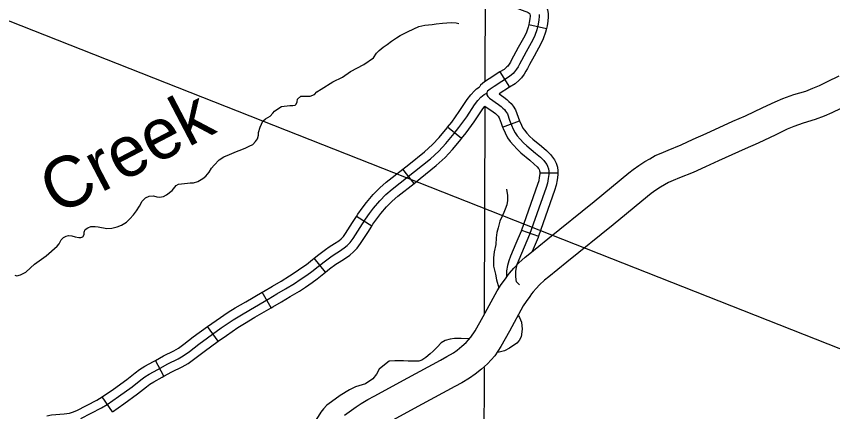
# Model space of a CAD drawing. Extents: x -3711 to 825, y -151 to 1050.
# Drawn here: x -2819.1 to -2743.1, y 325 to 361.8 of the extents above; entities that cross this region are included whole.
import ezdxf

# ---------------------------------------------------------------- set-up
doc = ezdxf.new("R2010")
doc.units = 0
for name, color, linetype in [('Level 10', 7, 'Continuous'), ('Level 32', 7, 'Continuous'), ('Level 35', 7, 'Continuous'), ('Level 5', 7, 'Continuous'), ('R_Dimension', 7, 'Continuous')]:
    doc.layers.add(name, color=color, linetype=linetype)

msp = doc.modelspace()

# ---------------------------------------------------------------- linework, layer by layer
at = {"layer": 'Level 10'}
for points in [[(-2788.528, 324.638), (-2787.441, 325.413), (-2786.955, 325.737), (-2786.36, 326.097), (-2785.754, 326.43), (-2782.623, 328.132), (-2779.582, 329.773), (-2778.996, 330.099), (-2778.387, 330.46), (-2778.024, 330.712), (-2777.586, 331.061), (-2777.207, 331.414), (-2776.745, 331.913), (-2776.368, 332.494), (-2775.603, 333.828), (-2774.296, 336.236), (-2773.934, 336.807), (-2773.544, 337.355), (-2773.352, 337.616), (-2773.155, 337.883), (-2772.765, 338.34), (-2772.29, 338.828), (-2771.7, 339.353), (-2771.274, 339.697), (-2769.576, 341.079), (-2765.277, 344.555), (-2762.057, 347.22), (-2761.633, 347.544), (-2761.114, 347.915), (-2760.566, 348.272), (-2760.102, 348.536), (-2759.587, 348.82), (-2759.033, 349.064), (-2758.395, 349.334), (-2757.177, 349.835), (-2756.06, 350.343), (-2754.853, 350.879), (-2752.358, 352.026), (-2751.177, 352.543), (-2749.574, 353.306), (-2748.427, 353.845), (-2747.704, 354.139), (-2746.688, 354.515), (-2745.583, 354.842), (-2744.912, 355.096), (-2744.302, 355.357), (-2743.556, 355.723), (-2742.47, 356.257)], [(-2742.321, 353.208), (-2743.134, 352.809), (-2743.864, 352.497), (-2744.688, 352.185), (-2745.803, 351.854), (-2746.69, 351.527), (-2747.303, 351.277), (-2748.376, 350.773), (-2750.012, 349.994), (-2751.21, 349.469), (-2753.699, 348.326), (-2754.911, 347.787), (-2756.064, 347.263), (-2757.317, 346.748), (-2757.922, 346.492), (-2758.342, 346.306), (-2758.733, 346.091), (-2759.107, 345.878), (-2759.533, 345.601), (-2759.966, 345.291), (-2760.312, 345.027), (-2763.503, 342.386), (-2767.811, 338.903), (-2769.51, 337.52), (-2769.888, 337.215), (-2770.352, 336.802), (-2770.692, 336.452), (-2770.96, 336.138), (-2771.097, 335.953), (-2771.273, 335.714), (-2771.608, 335.242), (-2771.879, 334.815), (-2773.155, 332.463), (-2773.976, 331.032), (-2774.527, 330.184), (-2775.22, 329.436), (-2775.753, 328.938), (-2776.352, 328.461), (-2776.872, 328.101), (-2777.6, 327.669), (-2778.236, 327.315), (-2781.289, 325.669), (-2784.41, 323.971)]]:
    msp.add_lwpolyline(points, dxfattribs=at)
at = {"layer": 'Level 32'}
for p, q in [((-2771.365, 361.028), (-2769.725, 360.659)), ((-2774.044, 356.615), (-2773.145, 355.194)), ((-2773.813, 351.485), (-2772.238, 352.075)), ((-2777.616, 350.412), (-2778.929, 351.462)), ((-2782.048, 346.231), (-2783.083, 347.557)), ((-2770.346, 347.223), (-2768.665, 347.223)), ((-2785.985, 342.259), (-2787.403, 343.161)), ((-2772.042, 341.868), (-2770.455, 341.312)), ((-2790.306, 337.953), (-2791.356, 339.265)), ((-2795.349, 334.643), (-2796.198, 336.095)), ((-2800.283, 331.531), (-2801.266, 332.895)), ((-2805.327, 328.273), (-2806.133, 329.748)), ((-2810.122, 324.971), (-2811.076, 326.355))]:
    msp.add_line(p, q, dxfattribs=at)
for points in [[(-2773.81, 365.162), (-2773.141, 364.731), (-2772.812, 364.536), (-2772.424, 364.332), (-2772.035, 364.183), (-2771.163, 363.859), (-2770.872, 363.756), (-2770.575, 363.607), (-2770.273, 363.406), (-2769.98, 363.125), (-2769.735, 362.744), (-2769.623, 362.394), (-2769.569, 362.048), (-2769.557, 361.744), (-2769.603, 361.353), (-2769.667, 360.915), (-2769.725, 360.659)], [(-2774.719, 363.748), (-2774.025, 363.301), (-2773.633, 363.068), (-2773.12, 362.799), (-2772.63, 362.61), (-2771.736, 362.278), (-2771.531, 362.206), (-2771.421, 362.151), (-2771.329, 362.089), (-2771.286, 362.049), (-2771.269, 362.021), (-2771.264, 362.006), (-2771.245, 361.885), (-2771.242, 361.81), (-2771.27, 361.573), (-2771.321, 361.223), (-2771.365, 361.028)], [(-2770.407, 361.967), (-2770.4, 361.777), (-2770.436, 361.463), (-2770.494, 361.069), (-2770.611, 360.551), (-2770.801, 360.015), (-2770.99, 359.602), (-2771.601, 358.493), (-2772.04, 357.693), (-2772.22, 357.344), (-2772.355, 357.107), (-2772.502, 356.87), (-2772.682, 356.622), (-2772.828, 356.476), (-2773.155, 356.183), (-2774.597, 355.27), (-2774.968, 355.011), (-2775.193, 354.83), (-2775.261, 354.706), (-2775.266, 354.649), (-2775.272, 354.582), (-2775.261, 354.481), (-2775.182, 354.334), (-2775.036, 354.177), (-2774.191, 353.579), (-2773.943, 353.399), (-2773.774, 353.252), (-2773.628, 353.117), (-2773.527, 352.971), (-2773.358, 352.711), (-2773.155, 352.125), (-2772.986, 351.674), (-2772.817, 351.302), (-2772.637, 350.93), (-2772.434, 350.66), (-2772.164, 350.344), (-2771.86, 350.006), (-2771.556, 349.724), (-2770.733, 349.048), (-2770.283, 348.665), (-2769.967, 348.361), (-2769.799, 348.158), (-2769.686, 348.011), (-2769.607, 347.831), (-2769.528, 347.583), (-2769.506, 347.369), (-2769.506, 347.076), (-2769.551, 346.681), (-2769.618, 346.264), (-2769.753, 345.858), (-2771.285, 341.485), (-2771.781, 340.302), (-2772.288, 339.118), (-2772.434, 338.758), (-2772.535, 338.419), (-2772.592, 338.014), (-2772.603, 337.597), (-2772.58, 337.258), (-2772.535, 337.101), (-2772.457, 336.999), (-2772.265, 336.819), (-2772.224, 336.784)], [(-2771.365, 361.028), (-2771.42, 360.785), (-2771.581, 360.331), (-2771.741, 359.981), (-2772.337, 358.898), (-2772.782, 358.088), (-2772.959, 357.745), (-2773.078, 357.537), (-2773.2, 357.339), (-2773.323, 357.17), (-2773.407, 357.086), (-2773.664, 356.855), (-2774.044, 356.615)], [(-2769.725, 360.659), (-2769.802, 360.318), (-2770.021, 359.699), (-2770.239, 359.224), (-2770.864, 358.089), (-2771.298, 357.298), (-2771.481, 356.942), (-2771.633, 356.677), (-2771.803, 356.401), (-2772.041, 356.075), (-2772.25, 355.865), (-2772.646, 355.51), (-2773.145, 355.194)], [(-2774.044, 356.615), (-2775.062, 355.97), (-2775.472, 355.684), (-2775.851, 355.381), (-2775.919, 355.256)], [(-2778.929, 351.462), (-2778.538, 351.95), (-2777.835, 352.925), (-2777.088, 354.053), (-2776.75, 354.494), (-2776.426, 354.854), (-2776.22, 355.039), (-2775.994, 355.211), (-2775.919, 355.256)], [(-2773.145, 355.194), (-2774.131, 354.57), (-2774.133, 354.568), (-2773.701, 354.262), (-2773.42, 354.057), (-2773.214, 353.879), (-2772.989, 353.672), (-2772.829, 353.439), (-2772.597, 353.084), (-2772.364, 352.41), (-2772.238, 352.075)], [(-2813.079, 324.32), (-2811.153, 325.325), (-2810.623, 325.647), (-2809.548, 326.387), (-2808.292, 327.294), (-2807.483, 327.937), (-2807.12, 328.216), (-2806.701, 328.468), (-2805.906, 328.915), (-2804.985, 329.417), (-2804.022, 329.892), (-2803.533, 330.171), (-2802.961, 330.59), (-2802.096, 331.261), (-2800.002, 332.769), (-2798.9, 333.523), (-2798.258, 333.914), (-2797.281, 334.487), (-2795.634, 335.451), (-2794.811, 335.939), (-2794.001, 336.414), (-2793.178, 336.917), (-2792.634, 337.28), (-2792.02, 337.699), (-2791.559, 338.02), (-2790.973, 338.495), (-2790.415, 338.942), (-2789.801, 339.389), (-2789.48, 339.612), (-2788.991, 339.92), (-2788.545, 340.227), (-2788.266, 340.464), (-2787.987, 340.744), (-2787.721, 341.107), (-2787.066, 342.126), (-2786.577, 342.894), (-2786.2, 343.425), (-2785.81, 343.942), (-2785.237, 344.626), (-2784.665, 345.199), (-2784.093, 345.702), (-2782, 347.336), (-2780.52, 348.537), (-2779.739, 349.249), (-2779.083, 349.947), (-2778.315, 350.883), (-2777.869, 351.442), (-2777.143, 352.447), (-2776.403, 353.564), (-2776.102, 353.956), (-2775.831, 354.258), (-2775.684, 354.39), (-2775.521, 354.514), (-2775.405, 354.584), (-2775.266, 354.649)], [(-2777.616, 350.412), (-2777.199, 350.933), (-2776.452, 351.969), (-2775.719, 353.076), (-2775.443, 353.435)], [(-2775.443, 353.435), (-2774.681, 352.896), (-2774.467, 352.74), (-2774.335, 352.626), (-2774.266, 352.563), (-2774.224, 352.502), (-2774.118, 352.339), (-2773.946, 351.84), (-2773.813, 351.485)], [(-2772.238, 352.075), (-2772.209, 351.996), (-2772.056, 351.66), (-2771.916, 351.37), (-2771.778, 351.186), (-2771.532, 350.899), (-2771.26, 350.597), (-2771.002, 350.358), (-2770.194, 349.693), (-2769.718, 349.288), (-2769.351, 348.934), (-2769.142, 348.683), (-2768.957, 348.442), (-2768.819, 348.127), (-2768.701, 347.756), (-2768.665, 347.413), (-2768.665, 347.223)], [(-2783.083, 347.557), (-2782.523, 347.993), (-2781.069, 349.174), (-2780.329, 349.848), (-2779.715, 350.502), (-2778.969, 351.412), (-2778.929, 351.462)], [(-2773.813, 351.485), (-2773.763, 351.353), (-2773.578, 350.945), (-2773.358, 350.491), (-2773.09, 350.134), (-2772.796, 349.79), (-2772.459, 349.416), (-2772.109, 349.091), (-2771.273, 348.403), (-2770.848, 348.042), (-2770.584, 347.788), (-2770.455, 347.632), (-2770.415, 347.58), (-2770.395, 347.534), (-2770.355, 347.41), (-2770.346, 347.325), (-2770.346, 347.223)], [(-2782.048, 346.231), (-2781.476, 346.678), (-2779.972, 347.899), (-2779.148, 348.65), (-2778.451, 349.392), (-2777.662, 350.354), (-2777.616, 350.412)], [(-2787.403, 343.161), (-2787.275, 343.364), (-2786.878, 343.922), (-2786.468, 344.465), (-2785.858, 345.194), (-2785.241, 345.812), (-2784.629, 346.349), (-2783.083, 347.557)], [(-2770.346, 347.223), (-2770.346, 347.124), (-2770.384, 346.796), (-2770.437, 346.466), (-2770.549, 346.13), (-2772.042, 341.868)], [(-2768.665, 347.223), (-2768.665, 347.028), (-2768.718, 346.566), (-2768.799, 346.063), (-2768.958, 345.587), (-2770.455, 341.312)], [(-2785.985, 342.259), (-2785.879, 342.425), (-2785.522, 342.928), (-2785.151, 343.418), (-2784.616, 344.058), (-2784.09, 344.585), (-2783.556, 345.054), (-2782.048, 346.231)], [(-2791.356, 339.265), (-2790.925, 339.61), (-2790.288, 340.074), (-2789.944, 340.314), (-2789.454, 340.622), (-2789.057, 340.895), (-2788.836, 341.083), (-2788.627, 341.292), (-2788.415, 341.582), (-2787.774, 342.579), (-2787.403, 343.161)], [(-2790.306, 337.953), (-2789.905, 338.274), (-2789.313, 338.704), (-2789.016, 338.911), (-2788.529, 339.217), (-2788.033, 339.559), (-2787.695, 339.846), (-2787.346, 340.195), (-2787.028, 340.631), (-2786.357, 341.673), (-2785.985, 342.259)], [(-2772.042, 341.868), (-2772.07, 341.787), (-2772.555, 340.63), (-2773.063, 339.442), (-2773.228, 339.037), (-2773.359, 338.599), (-2773.431, 338.083), (-2773.447, 337.487)], [(-2770.455, 341.312), (-2770.5, 341.184), (-2771.044, 339.884)], [(-2796.198, 336.095), (-2796.061, 336.175), (-2795.238, 336.663), (-2794.433, 337.136), (-2793.631, 337.626), (-2793.104, 337.977), (-2792.497, 338.391), (-2792.065, 338.692), (-2791.5, 339.15), (-2791.356, 339.265)], [(-2795.349, 334.643), (-2795.207, 334.726), (-2794.384, 335.215), (-2793.57, 335.693), (-2792.726, 336.208), (-2792.164, 336.583), (-2791.542, 337.007), (-2791.054, 337.348), (-2790.446, 337.84), (-2790.305, 337.953)], [(-2801.266, 332.895), (-2800.485, 333.457), (-2799.356, 334.23), (-2798.689, 334.636), (-2797.706, 335.212), (-2796.198, 336.095)], [(-2800.283, 331.531), (-2799.519, 332.081), (-2798.444, 332.817), (-2797.827, 333.193), (-2796.856, 333.762), (-2795.349, 334.643)], [(-2806.133, 329.748), (-2805.372, 330.164), (-2804.416, 330.635), (-2803.992, 330.878), (-2803.467, 331.262), (-2802.599, 331.934), (-2801.266, 332.895)], [(-2805.327, 328.273), (-2804.597, 328.671), (-2803.627, 329.15), (-2803.075, 329.465), (-2802.455, 329.919), (-2801.592, 330.587), (-2800.283, 331.531)], [(-2811.076, 326.355), (-2810.033, 327.074), (-2808.8, 327.965), (-2808, 328.599), (-2807.594, 328.912), (-2807.123, 329.195), (-2806.313, 329.65), (-2806.133, 329.748)], [(-2810.122, 324.971), (-2809.063, 325.7), (-2807.784, 326.624), (-2806.965, 327.275), (-2806.645, 327.521), (-2806.279, 327.741), (-2805.498, 328.179), (-2805.327, 328.273)], [(-2816.24, 324.595), (-2815.795, 324.665), (-2814.625, 324.779), (-2814.366, 324.804), (-2814.129, 324.847), (-2813.844, 324.924), (-2813.427, 325.086), (-2811.566, 326.058), (-2811.079, 326.353), (-2811.076, 326.355)]]:
    msp.add_lwpolyline(points, dxfattribs=at)
at = {"layer": 'Level 35'}
for points in [[(-2792.939, 353.835), (-2792.891, 354.079), (-2792.597, 354.361), (-2792.231, 354.373), (-2791.926, 354.348), (-2791.706, 354.361), (-2791.327, 354.507), (-2791.095, 354.764), (-2790.692, 355.021), (-2789.605, 355.681), (-2788.713, 356.145), (-2787.956, 356.646), (-2786.71, 357.307), (-2785.83, 357.942), (-2785.549, 358.37), (-2785.293, 358.627), (-2784.926, 358.92), (-2784.56, 359.189), (-2784.145, 359.482), (-2783.68, 359.788), (-2783.338, 360.02), (-2782.642, 360.363), (-2782.068, 360.644), (-2781.592, 360.839), (-2781.054, 360.986), (-2780.346, 361.047), (-2779.979, 361.096), (-2779.393, 361.157), (-2778.599, 361.218), (-2778.11, 361.194), (-2777.891, 361.145)], [(-2819.226, 337.687), (-2819.031, 337.626), (-2818.676, 337.712), (-2818.188, 337.956), (-2817.76, 338.36), (-2817.369, 338.702), (-2816.307, 339.496), (-2815.268, 340.376), (-2815.085, 340.621), (-2814.89, 340.975), (-2814.67, 341.208), (-2814.45, 341.318), (-2814.23, 341.367), (-2813.912, 341.354), (-2813.583, 341.269), (-2813.265, 341.208), (-2813.057, 341.183), (-2812.874, 341.257), (-2812.764, 341.489), (-2812.764, 341.684), (-2812.654, 341.929), (-2812.41, 342.1), (-2812.154, 342.21), (-2811.726, 342.222), (-2811.457, 342.198), (-2810.651, 342.039), (-2810.187, 342.063), (-2809.686, 342.198), (-2809.271, 342.344), (-2808.819, 342.638), (-2808.513, 342.919), (-2808.159, 343.298), (-2807.878, 343.689), (-2807.61, 344.129), (-2807.353, 344.569), (-2807.06, 344.887), (-2806.693, 345.058), (-2806.303, 345.083), (-2805.997, 344.985), (-2805.741, 344.96), (-2805.386, 345.009), (-2805.093, 345.156), (-2804.556, 345.584), (-2804.189, 346.036), (-2803.969, 346.158), (-2803.139, 346.268), (-2802.895, 346.281), (-2802.577, 346.281), (-2802.162, 346.403), (-2801.722, 346.684), (-2801.429, 346.916), (-2801.111, 347.295), (-2800.904, 347.65), (-2800.647, 347.943), (-2800.183, 348.432), (-2799.755, 348.713), (-2799.218, 348.933), (-2798.583, 349.202), (-2798.082, 349.398), (-2797.703, 349.557), (-2797.386, 349.703), (-2797.056, 349.862), (-2796.799, 350.131), (-2796.616, 350.376), (-2796.531, 350.718), (-2796.518, 350.962), (-2796.384, 351.476), (-2796.127, 352.026), (-2795.871, 352.246), (-2795.443, 352.503), (-2795.199, 352.771), (-2795.04, 352.967), (-2794.833, 353.126), (-2794.393, 353.395), (-2794.136, 353.444), (-2793.868, 353.468), (-2793.599, 353.48), (-2793.342, 353.48), (-2793.123, 353.529), (-2793.025, 353.627), (-2792.939, 353.835)], [(-2773.448, 345.703), (-2773.349, 345.106), (-2773.349, 344.642), (-2773.415, 344.245), (-2773.548, 343.847), (-2773.68, 343.516), (-2773.846, 343.185), (-2774.044, 342.721), (-2774.144, 342.356), (-2774.21, 342.091), (-2774.342, 341.661), (-2774.409, 341.164), (-2774.442, 340.534), (-2774.574, 339.872), (-2774.64, 339.308), (-2774.64, 338.878), (-2774.64, 338.513), (-2774.475, 337.784), (-2774.375, 337.254), (-2774.15, 336.522)], [(-2772.328, 333.889), (-2772.226, 333.746), (-2772.029, 333.295), (-2771.98, 332.647), (-2772.087, 331.957), (-2772.244, 331.61), (-2772.49, 331.352), (-2773.151, 330.881), (-2773.633, 330.634), (-2774.114, 330.522), (-2774.31, 330.494)], [(-2776.944, 331.759), (-2777.651, 331.786), (-2778.275, 331.787), (-2778.676, 331.73), (-2779.135, 331.596), (-2779.525, 331.373), (-2779.889, 330.975), (-2780.254, 330.611), (-2780.552, 330.346), (-2780.949, 330.015), (-2781.313, 329.783), (-2781.611, 329.683), (-2782.108, 329.683), (-2782.604, 329.683), (-2783.034, 329.716), (-2783.498, 329.716), (-2783.829, 329.716), (-2784.359, 329.683), (-2784.657, 329.451), (-2785.286, 328.921), (-2785.551, 328.457), (-2785.882, 328.027), (-2786.577, 327.563), (-2787.504, 327.298), (-2788.067, 327), (-2788.927, 326.47), (-2789.722, 325.873), (-2790.158, 325.575)], [(-2790.158, 325.575), (-2790.473, 325.238), (-2790.738, 324.913), (-2790.974, 324.53), (-2791.375, 323.903), (-2791.938, 323.274), (-2792.633, 322.843), (-2793.925, 322.147), (-2794.719, 321.816), (-2795.183, 321.551), (-2795.547, 321.319), (-2796.507, 320.358), (-2797.079, 319.438), (-2797.376, 319.084), (-2797.674, 318.898), (-2798.009, 318.805), (-2798.344, 318.693), (-2798.772, 318.433), (-2799.051, 318.228), (-2799.242, 318.008)]]:
    msp.add_lwpolyline(points, dxfattribs=at)
at = {"layer": 'Level 5'}
for points in [[(-2775.435, 364.195), (-2775.455, 355.748)], [(-2775.46, 353.39), (-2775.506, 334.093)], [(-2775.518, 329.072), (-2775.536, 321.571), (-2774.964, 292.769)]]:
    msp.add_lwpolyline(points, dxfattribs=at)
at = {"layer": 'R_Dimension'}
msp.add_line((-2469.437, 223.07), (-2866.636, 379.848), dxfattribs=at)

# ---------------------------------------------------------------- texts
at = {"layer": 'Level 35'}
msp.add_text('Creek', height=4.7343, rotation=27.60193, dxfattribs=at).set_placement((-2815.258, 343.215))

doc.saveas('drawing.dxf')
